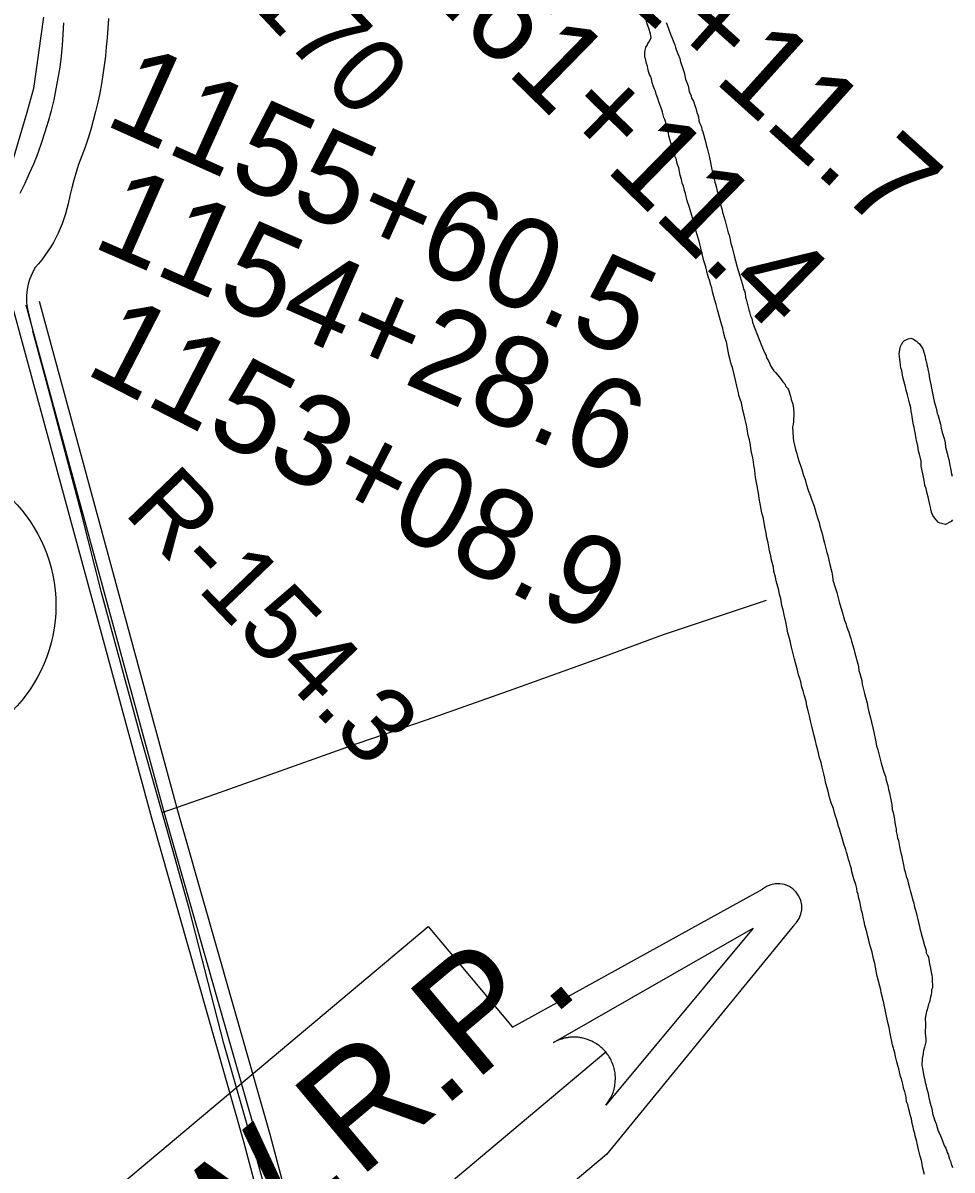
# Model space of a CAD drawing. Extents: x 3424494 to 3462436, y 522220 to 547718.
# Drawn here: x 3453024 to 3454050, y 543347 to 544612 of the extents above; entities that cross this region are included whole.
import ezdxf

# ---------------------------------------------------------------- set-up
doc = ezdxf.new("R2010")
doc.units = 0
for name, color, linetype in [('V-DTCH-CNTR', 7, 'Continuous'), ('V-RIVR-EDGE', 7, 'Continuous'), ('V-RIVR-RANG-IDEN', 7, 'Continuous'), ('V-ROAD-CNTR', 7, 'Continuous'), ('V-ROAD-IDEN', 7, 'Continuous'), ('V-SITE-VEGE', 7, 'Continuous'), ('V-SURV-IDEN', 7, 'Continuous'), ('V-TOPO-SHOR', 7, 'Continuous'), ('V-TOPO-WATR-IDEN', 7, 'Continuous')]:
    doc.layers.add(name, color=color, linetype=linetype)

msp = doc.modelspace()

# ---------------------------------------------------------------- linework, layer by layer
at = {"layer": 'V-DTCH-CNTR'}
for points in [[(3453118.5, 544617.4), (3453117.8, 544606.8), (3453116.9, 544596.2), (3453116.1, 544586), (3453115.1, 544575.7), (3453113.8, 544565.5), (3453112.4, 544555.3), (3453110.7, 544545.1), (3453108.8, 544535), (3453106.6, 544524.9), (3453104.3, 544514.9), (3453101.7, 544504.9), (3453098.9, 544495)], [(3453098.9, 544495), (3453095.9, 544485.2), (3453092.6, 544475.4), (3453089.2, 544465.7), (3453085.5, 544456.1), (3453082.7, 544447.6), (3453080.2, 544439), (3453077.9, 544430.3), (3453075.8, 544421.6), (3453073.9, 544412.9), (3453072.6, 544407.3), (3453071.1, 544401.8), (3453069.3, 544396.3), (3453067.4, 544390.9), (3453065.3, 544385.6), (3453062.9, 544380.4), (3453060.4, 544375.3), (3453057.7, 544370.2), (3453054.8, 544365.3), (3453051.7, 544360.5), (3453048.4, 544355.8), (3453045, 544351.2), (3453041.4, 544346.7), (3453037.6, 544342.4), (3453035.8, 544339.3), (3453034.1, 544336.1), (3453032.7, 544332.7), (3453031.4, 544329.3), (3453030.3, 544325.8), (3453029.4, 544322.3), (3453028.8, 544318.7), (3453028.3, 544315.1), (3453028, 544311.5), (3453028, 544307.9), (3453028.1, 544304.2)], [(3453028.1, 544304.2), (3453028.5, 544300.6), (3453029.1, 544297), (3453029.8, 544293.5), (3453034.8, 544272.3)], [(3453526.6, 542482.9), (3453494.5, 542596.8), (3453463.8, 542702.4), (3453443.7, 542773.5), (3453435, 542805), (3453408.4, 542903.2), (3453375.2, 543018.6), (3453344.3, 543135.1), (3453312.5, 543248.5), (3453281.6, 543361.9), (3453245.8, 543486.2), (3453207.7, 543635), (3453182.9, 543723.1), (3453177.7, 543741.2), (3453154.1, 543824.1), (3453111.1, 543982.6), (3453088.3, 544072.7), (3453054.8, 544198.9), (3453034.8, 544272.3)], [(3453177.7, 543741.2), (3453236, 543761.5), (3453318.8, 543790.6), (3453393.1, 543817.2), (3453470.8, 543843.7), (3453565.2, 543877.2), (3453663.6, 543912.7), (3453731.2, 543937.4), (3453788.7, 543956.5), (3453844.8, 543975.4)]]:
    msp.add_lwpolyline(points, dxfattribs=at)
at = {"layer": 'V-RIVR-EDGE'}
msp.add_spline([(3451748, 544260.9), (3451764.4, 544271.1), (3451791.5, 544289.6), (3451819.7, 544315.2), (3451837, 544333.4), (3451853.4, 544346.5), (3451865.5, 544357.5), (3451883.9, 544373.5), (3451891.9, 544381.9), (3451901.8, 544389.5), (3451915.4, 544400.1), (3451929.3, 544415.4), (3451940.3, 544428.2), (3451954.2, 544444.2), (3451972.9, 544464.7), (3451993.4, 544482.9), (3452012.5, 544495.6), (3452023.8, 544502.9), (3452039.2, 544516.4), (3452050.2, 544527), (3452059, 544538.3), (3452067.8, 544552.9), (3452074.8, 544560.5), (3452091.2, 544571.8), (3452115.8, 544592.6), (3452128.2, 544602.8), (3452139.6, 544615.2), (3452155, 544628.3), (3452167.4, 544638.5), (3452179.9, 544650.9), (3452198.2, 544669.2), (3452207.8, 544682.3), (3452220.6, 544695.1), (3452238.5, 544714), (3452251, 544727.5), (3452258.3, 544734.8), (3452278.1, 544758.5), (3452293.2, 544775.7), (3452312.6, 544794.6), (3452329.8, 544810.7), (3452335.3, 544823.1), (3452350, 544839.5), (3452364.7, 544859.2), (3452384.1, 544880), (3452409.4, 544913.9), (3452420.8, 544928.9), (3452427.4, 544943.5), (3452428.9, 544959.2), (3452432.2, 544966.5), (3452437.7, 544973.4), (3452456.7, 544992), (3452476.9, 545011.7), (3452493, 545024.9), (3452500.7, 545030.3), (3452509.5, 545042), (3452516.5, 545052.2), (3452530.4, 545063.1), (3452544.7, 545071.1), (3452550.5, 545081), (3452571.8, 545108.4), (3452596, 545136.1), (3452616.9, 545156.9), (3452640.7, 545180.6), (3452668.6, 545210.5), (3452708.1, 545250.6), (3452727.2, 545267), (3452748.8, 545279.4), (3452766.7, 545292.1), (3452778.5, 545308.2), (3452791.7, 545319.1), (3452841.5, 545350.8), (3452868.2, 545377), (3452890.6, 545399.3), (3452902.6, 545409.1), (3452913.3, 545420.1), (3452931.6, 545429.9), (3452944.8, 545441.2), (3452999.7, 545489.3), (3453027.2, 545515.6), (3453069, 545555.7), (3453103.4, 545592.5), (3453125.8, 545625.7), (3453154.4, 545652.3), (3453181.9, 545679.7), (3453207.5, 545702.3), (3453239.4, 545730.7), (3453267.7, 545752.5)], degree=3, dxfattribs=at)
at = {"layer": 'V-ROAD-CNTR'}
for points in [[(3453012.8, 544297.5), (3453165.8, 543735.1), (3453267.7, 543378.2), (3453416, 542818.1)], [(3453027.3, 544301.5), (3453180.3, 543739.2), (3453282.2, 543382.2), (3453431.5, 542817.9), (3453579.8, 542281.3), (3453694, 541871.9), (3453701.2, 541849.5)], [(3453041.8, 544305.4), (3453194.7, 543743.2), (3453296.6, 543386.2), (3453444.3, 542828.2)]]:
    msp.add_lwpolyline(points, dxfattribs=at)
msp.add_arc((3452629.4, 544625.1), 439.9, 332.8686, 358.3473, dxfattribs=at)
at = {"layer": 'V-ROAD-IDEN'}
msp.add_circle((3452895.4, 543969.7), 165, dxfattribs=at)
at = {"layer": 'V-SITE-VEGE'}
for points in [[(3453813.9, 544204.2), (3453812.1, 544211.5), (3453811, 544216.6), (3453807.4, 544232.1), (3453805.9, 544235.9), (3453804.5, 544242.1), (3453803.4, 544246), (3453800.5, 544260.4), (3453799.1, 544264.2), (3453797.3, 544271.2), (3453796.6, 544275.5), (3453795.1, 544280.1), (3453792.5, 544289.4), (3453790.7, 544295.7), (3453789.3, 544301.9), (3453787.8, 544306.5), (3453786.7, 544310.4), (3453785.3, 544315.8), (3453784.6, 544320.1), (3453783.5, 544323.2), (3453782, 544328.6), (3453780.9, 544331.7), (3453779.8, 544335.2), (3453778, 544343.4), (3453775.8, 544350), (3453770.4, 544371.7), (3453767.8, 544379.8), (3453764.9, 544389.9), (3453763.1, 544397.3), (3453759.8, 544408.9), (3453757.2, 544416.3), (3453755.4, 544424.4), (3453754.3, 544427.5), (3453753.3, 544432.2), (3453751.8, 544435.7), (3453751.1, 544439.6), (3453749.6, 544444.6), (3453748.2, 544452.4), (3453746.7, 544456.2), (3453746, 544458.6), (3453745.3, 544461.7), (3453744.1, 544464.8), (3453742, 544472.2), (3453740.1, 544477.6), (3453737.2, 544487.7), (3453736.5, 544490.8), (3453734.7, 544497), (3453734.3, 544499.3), (3453733.6, 544502.4), (3453732.5, 544505.9), (3453731.4, 544508.2), (3453729.9, 544514.1), (3453729.2, 544516.4), (3453728.4, 544518.3), (3453727.7, 544520.7), (3453725.9, 544525.3), (3453724.8, 544529.2), (3453722.9, 544533.9), (3453722.2, 544537), (3453721.1, 544539.3), (3453719.6, 544543.2), (3453718.5, 544546.7), (3453717.8, 544550.6), (3453716.7, 544553.7), (3453715.6, 544555.6), (3453714.8, 544557.6), (3453714.1, 544560.3), (3453713.4, 544564.9), (3453712.3, 544567.6), (3453711.6, 544571.5), (3453710.5, 544575), (3453710.6, 544580.4), (3453711.4, 544583.5), (3453711.8, 544585.8), (3453713, 544587.7), (3453713.8, 544589.6), (3453715.4, 544591.5), (3453717.4, 544596.5), (3453716.7, 544600), (3453714.9, 544606.6), (3453713, 544611.6), (3453711.6, 544617.1)], [(3453733.9, 544612.8), (3453736.5, 544606.2), (3453739.1, 544598.8), (3453740.6, 544595.7), (3453741.7, 544592.6), (3453743.5, 544588.3), (3453744.2, 544585.2), (3453745.4, 544582.1), (3453749.1, 544573.2), (3453749.8, 544569.7), (3453752.7, 544561.2), (3453753.8, 544557.7), (3453755.6, 544550.3), (3453758.2, 544542.9), (3453759.6, 544536.7), (3453761.5, 544532.1), (3453762.2, 544529.3), (3453764.1, 544526.2), (3453765.6, 544521.2), (3453766.7, 544518.5), (3453767.8, 544513.8)], [(3453767.8, 544513.8), (3453768.9, 544511.1), (3453769.6, 544508.8), (3453770.3, 544504.5), (3453771, 544502.2), (3453772.9, 544497.9), (3453773.6, 544494.8), (3453774.7, 544492.1), (3453778, 544480), (3453778.7, 544476.6), (3453779.4, 544474.2), (3453781.2, 544466.9), (3453782, 544463.8), (3453784.8, 544449), (3453786.6, 544441.7), (3453787.7, 544436.6), (3453788.4, 544434.7), (3453789.5, 544430.4), (3453790.2, 544426.9), (3453791.3, 544423.8), (3453793.1, 544415.7), (3453795.7, 544407.2), (3453796.4, 544403.7), (3453798.2, 544397.8), (3453799.3, 544394), (3453802.6, 544380.8), (3453803.7, 544378.1), (3453804.4, 544375.3), (3453805.5, 544369.2), (3453806.9, 544364.5), (3453809.5, 544354), (3453813.1, 544340.5), (3453815.7, 544332.3), (3453817.9, 544324.9), (3453818.6, 544322.2), (3453819.3, 544318.7), (3453820.4, 544316.8), (3453821.1, 544314.1), (3453821.8, 544309.8), (3453822.9, 544306.3), (3453825.5, 544295.8), (3453826.2, 544293.5), (3453827.3, 544289.2), (3453828.8, 544286.1), (3453829.5, 544282.3), (3453831.3, 544277.2), (3453832.8, 544273.3), (3453834.3, 544269.8), (3453836.1, 544264.8), (3453837.6, 544261.3), (3453838.7, 544258.2), (3453841.7, 544251.2), (3453843.2, 544247.3), (3453844.3, 544245.3), (3453845, 544243), (3453846.9, 544239.5), (3453848.4, 544236.4), (3453849.1, 544234.1), (3453852.9, 544228.6), (3453854.8, 544226.6), (3453859, 544221.5), (3453862.7, 544216.5), (3453865, 544214.1), (3453866.1, 544211.4), (3453868, 544209.4), (3453869.2, 544207.5), (3453871.4, 544200.5), (3453872.1, 544197), (3453873.9, 544191.9), (3453874.6, 544186.9), (3453874.9, 544182.3), (3453874.7, 544172.2), (3453874.3, 544169.5), (3453873.5, 544166.9), (3453874.4, 544154.5), (3453874.8, 544151.4), (3453876.9, 544141.7), (3453878.4, 544137.4), (3453879.1, 544133.9), (3453880.9, 544128.1), (3453882.4, 544124.2), (3453883.9, 544119.6), (3453885.7, 544113), (3453887.6, 544108.7), (3453888.6, 544104), (3453891.2, 544095.9), (3453893.1, 544091.2), (3453894.9, 544085.8), (3453897.5, 544079.2), (3453899.7, 544071), (3453901.5, 544065.2), (3453903, 544061.3), (3453903.7, 544057.1), (3453905.5, 544051.3), (3453906.6, 544047.4), (3453907.3, 544043.9), (3453908.8, 544038.5), (3453911.3, 544028), (3453912.4, 544024.9), (3453914.2, 544016.4), (3453917.1, 544006.3)], [(3454050.1, 544064.1), (3454048.6, 544062.2), (3454046.6, 544061.1), (3454042.3, 544058.8), (3454036.6, 544060.5), (3454034.7, 544061.3), (3454032, 544064), (3454030.1, 544066.3), (3454028.6, 544068.7), (3454027.1, 544072.6), (3454026.4, 544075.7), (3454025.7, 544078), (3454025, 544081.1), (3454023.9, 544085.7), (3454023.2, 544089.6), (3454022.1, 544093.1), (3454021, 544098.5), (3454019.6, 544102), (3454019.2, 544105.5), (3454017.5, 544114.7), (3454015.7, 544123.2), (3454015.7, 544126.3), (3454015.4, 544129), (3454013.6, 544136.4), (3454012.5, 544139.9), (3454011.8, 544146), (3454010.7, 544149.9), (3454009.7, 544155.7), (3454009.3, 544158.8), (3454008.6, 544161.9), (3454007.9, 544166.2), (3454007.2, 544168.5), (3454006.8, 544171.2), (3454006.1, 544175), (3454005.8, 544178.1), (3454005.1, 544180.5), (3454004.7, 544183.9), (3454004, 544187.8), (3454002.9, 544191.7), (3454000.4, 544202.1), (3453999, 544207.2), (3453998.3, 544211), (3453997.5, 544213.3), (3453995.4, 544221.5), (3453994.3, 544228.8), (3453993.2, 544231.9), (3453992.9, 544234.6), (3453992.2, 544238.5), (3453991.5, 544243.9), (3453991.2, 544247.4), (3453992, 544252), (3453992.8, 544255.4), (3453993.7, 544257.7), (3453995.2, 544260), (3453997.2, 544261.9), (3453999.5, 544263), (3454001.5, 544263.8), (3454004.2, 544264.5), (3454006.5, 544263.7), (3454010.3, 544261.3), (3454011.8, 544259.7), (3454013.7, 544258.2), (3454016, 544255), (3454017.5, 544252.7), (3454020, 544244.2), (3454020.4, 544241.5), (3454021.5, 544237.6), (3454021.8, 544235.3), (3454022.5, 544232.6), (3454023.2, 544228.7), (3454023.9, 544225.6), (3454024.6, 544220.2), (3454026.1, 544213.3), (3454027.5, 544207.4), (3454030, 544194.7), (3454032.2, 544187.3), (3454033.2, 544181.9), (3454034.3, 544178.8), (3454036.9, 544169.5), (3454037.6, 544165.3), (3454038.7, 544160.6), (3454040.9, 544153.7)], [(3453949.1, 543637), (3453947.7, 543642.8), (3453946.6, 543646.3), (3453945.9, 543651), (3453944.8, 543653.7), (3453944.4, 543657.2), (3453943.4, 543661.8), (3453941.1, 543668), (3453939, 543675.8), (3453938.6, 543678.9), (3453937.2, 543683.2), (3453936.4, 543686.3), (3453935.3, 543689.4), (3453934.2, 543694), (3453933.1, 543697.5), (3453932.4, 543700.2), (3453930.6, 543704.9), (3453928, 543714.2), (3453926.6, 543718.9), (3453925.5, 543723.1), (3453924.4, 543725.8), (3453923.6, 543728.9), (3453922.2, 543734), (3453921.1, 543737.1), (3453920, 543740.6), (3453918.9, 543745.6), (3453916.3, 543751.8), (3453914.1, 543759.2), (3453913, 543764.6), (3453910.5, 543773.2), (3453909.4, 543779), (3453908, 543783.7), (3453906.2, 543791), (3453905.1, 543796.1), (3453903.2, 543801.5), (3453901.5, 543810), (3453900, 543815.1), (3453898.9, 543820.1), (3453897.1, 543827.1), (3453894.6, 543837.9), (3453893.5, 543842.2), (3453892.8, 543846.1), (3453891, 543853.4), (3453889.5, 543858.9), (3453888.5, 543863.9), (3453886.3, 543870.9), (3453885.2, 543875.5), (3453883.7, 543879.4), (3453882.6, 543885.2), (3453881.6, 543889.1), (3453880.1, 543893), (3453878.6, 543899.6), (3453875.7, 543910.4), (3453872.1, 543925.2), (3453871.1, 543930.6), (3453868.5, 543939.5), (3453867.1, 543945.7), (3453866, 543951.5), (3453864.2, 543959.3), (3453863.1, 543964.7), (3453861.7, 543969.4), (3453860.6, 543977.1), (3453859.2, 543981.8), (3453858.5, 543986.4), (3453856.7, 543992.6), (3453855.6, 543996.9), (3453854.9, 544000.8), (3453853, 544007.4), (3453852.4, 544012), (3453850.5, 544019.4), (3453849.5, 544024.4), (3453848, 544029.8), (3453846.6, 544038.7), (3453845.2, 544044.2), (3453844.5, 544049.2), (3453843.1, 544056.2), (3453841.7, 544065.5), (3453839.8, 544071.7), (3453839.1, 544075.9), (3453836.6, 544087.6), (3453836.3, 544091.4), (3453834.6, 544101.5), (3453832.8, 544110.8), (3453832.5, 544114.6), (3453831.8, 544118.9), (3453830.7, 544124.3), (3453830.4, 544128.2), (3453829.7, 544132.5), (3453828.2, 544138.7), (3453827.5, 544142.9), (3453827.2, 544146.8), (3453826.1, 544152.2), (3453825, 544156.1), (3453824.3, 544159.2), (3453823.6, 544164.6), (3453822.6, 544168.5), (3453820, 544179.7), (3453818.6, 544185.2), (3453817.2, 544193.3), (3453814.2, 544201.4), (3453813.9, 544204.2)], [(3454040.9, 544153.7), (3454041.9, 544149), (3454042.6, 544144.4), (3454044.1, 544137.8), (3454045.1, 544134.3)], [(3454045.1, 544134.3), (3454046.2, 544130.8), (3454046.9, 544126.6), (3454047.3, 544123.9), (3454048, 544121.2), (3454049.1, 544115), (3454049.8, 544112.3)], [(3453917.1, 544006.3), (3453917.8, 544002), (3453918.1, 543997.8), (3453920, 543991.6), (3453922.5, 543983.8), (3453925.1, 543973.7), (3453928, 543963.6), (3453929.1, 543960.1), (3453929.8, 543957), (3453931.3, 543952.4), (3453932.4, 543949.6), (3453933.1, 543946.9), (3453934.6, 543942.7), (3453935.7, 543940.3), (3453936.4, 543937.6), (3453937.9, 543933.3), (3453938.6, 543930.2), (3453941.2, 543921.7), (3453942.3, 543917), (3453945.5, 543905), (3453946.2, 543901.9), (3453946.9, 543897.7), (3453947.7, 543894.6), (3453949.9, 543886.8), (3453950.6, 543882.9), (3453953.1, 543872.5), (3453956, 543861.6), (3453956.7, 543857), (3453957.8, 543852.3), (3453959.6, 543845.7), (3453963.2, 543829.8), (3453965.3, 543820.9), (3453966.4, 543814.7), (3453967.9, 543810.4), (3453971.5, 543795.7), (3453972.6, 543791.8), (3453974.4, 543785.6), (3453976.3, 543781), (3453977, 543776.7), (3453978.8, 543770.9), (3453979.5, 543766.6), (3453980.6, 543762.7), (3453981.6, 543756.9), (3453983.1, 543750), (3453983.7, 543744.5), (3453984.5, 543741), (3453986.3, 543733.7), (3453986.6, 543730.2), (3453987.3, 543725.9), (3453988, 543723.2), (3453988, 543720.1), (3453989.1, 543715.9), (3453989.4, 543712.8), (3453990.5, 543710.1), (3453991.5, 543703.5), (3453992.3, 543700), (3453994.1, 543692.2), (3453994.8, 543688.4), (3453996.2, 543683.3), (3453996.9, 543679.1), (3453998, 543675.6), (3453999.1, 543670.5), (3454000.6, 543667), (3454001.3, 543663.5), (3454002.8, 543658.1), (3454003.5, 543655), (3454004.9, 543650), (3454006.4, 543644.2), (3454007.5, 543641), (3454008.2, 543636.8), (3454009.3, 543633.3), (3454010, 543630.6), (3454012.5, 543619.7), (3454013.6, 543615.8), (3454014, 543613.1), (3454015.1, 543609.3), (3454015.8, 543606.2), (3454017.6, 543600), (3454019.1, 543594.5), (3454020.9, 543588.7), (3454021.2, 543586.4), (3454022.7, 543583.3), (3454023.5, 543581.3), (3454024.5, 543576.3), (3454024.9, 543574), (3454026, 543569.3), (3454026.7, 543564.7), (3454027.4, 543561.9), (3454027.7, 543558.9), (3454027.6, 543553.8), (3454028, 543551.5), (3454027.9, 543547.7), (3454027.1, 543545.4), (3454027.1, 543543), (3454026.6, 543540), (3454025.8, 543537.7), (3454024.6, 543531.9), (3454023.8, 543529.6), (3454022.1, 543523.4), (3454021.3, 543521.5), (3454020.4, 543516.1)], [(3454019.4, 543341.6), (3454016.9, 543350.2), (3454016.5, 543352.9), (3454015.8, 543357.1), (3454014.4, 543361.8), (3454012.6, 543369.2), (3454011.1, 543375.7), (3454010.8, 543378.1), (3454009, 543384.3), (3454008.6, 543387), (3454007.1, 543391.2), (3454006.8, 543394.3), (3454005.7, 543397.8), (3454005, 543402.9), (3454003.9, 543406.4), (3454003.2, 543409.8), (3454001.4, 543415.3), (3454000.7, 543418.8), (3453999.5, 543421.9), (3453998.9, 543426.9), (3453997.4, 543432.7), (3453995.9, 543437), (3453995.6, 543439.7), (3453994.9, 543442.8), (3453993.8, 543447.1), (3453992.7, 543449.8), (3453990.9, 543458.3), (3453989.8, 543461.8), (3453988.7, 543466.1), (3453987.3, 543471.9), (3453986.6, 543475.8), (3453984, 543484.7), (3453981.5, 543497.1), (3453980.1, 543503.7), (3453978.6, 543509.5), (3453974.4, 543530.8), (3453972.9, 543537), (3453971.5, 543542.4), (3453971.1, 543545.5), (3453967.5, 543559.1), (3453966.8, 543562.2), (3453964.3, 543574.6), (3453962.8, 543579.6), (3453961.4, 543587), (3453959.6, 543592.8), (3453958.5, 543596.7), (3453957.8, 543600.2), (3453956.3, 543605.6), (3453955.6, 543609.5), (3453954.1, 543614.1), (3453953.4, 543616.9), (3453952.7, 543620.7), (3453952, 543623.8), (3453950.9, 543629.6), (3453949.8, 543633.1), (3453949.1, 543637)], [(3454020.4, 543516.1), (3454020, 543513.4), (3454020.3, 543507.6), (3454020.1, 543497.2), (3454020.8, 543491.8), (3454020.7, 543487.9), (3454019.1, 543482.2), (3454018.3, 543478.3), (3454017.4, 543472.9), (3454016.6, 543469.5), (3454016.4, 543461.8), (3454017.2, 543459), (3454017.5, 543456.3), (3454018.6, 543450.1), (3454019.3, 543447.4), (3454020, 543443.5), (3454020.7, 543440.8), (3454021.4, 543437.3), (3454022.9, 543432.3), (3454024.3, 543424.9), (3454026.1, 543417.6), (3454027.2, 543414.5), (3454027.6, 543411.4), (3454028.6, 543407.5), (3454029.4, 543404.4), (3454030.1, 543402.1), (3454032, 543397.4), (3454034.5, 543389.6), (3454035.6, 543387.7), (3454037.1, 543383.4), (3454041.2, 543372.9), (3454042.7, 543370.6), (3454043.4, 543368.6), (3454044.2, 543365.9), (3454045.3, 543364), (3454046.7, 543358.5), (3454047.9, 543356.2), (3454048.6, 543353.5), (3454050.1, 543349.2)]]:
    msp.add_lwpolyline(points, dxfattribs=at)
at = {"layer": 'V-TOPO-SHOR'}
msp.add_lwpolyline([(3453046.6, 544618.7), (3453035.7, 544540.1), (3453028.4, 544513.5), (3453022.6, 544493.7), (3453013.2, 544462.4), (3453003.8, 544434.5), (3452991, 544404.5), (3452970.6, 544376.8), (3452932, 544317.2), (3452925, 544309.1), (3452798.9, 544183.8), (3452667.9, 544048.3), (3452537.5, 543911.4), (3452402.3, 543769.9), (3452229.5, 543596.7), (3452099.2, 543461.9), (3452035.1, 543395.9), (3451996.9, 543365.7)], dxfattribs=at)
at = {"layer": 'V-TOPO-WATR-IDEN'}
msp.add_line((3453091.7, 542994.2), (3453667.3, 543476.8), dxfattribs=at)
for points in [[(3452884.6, 542855.1), (3453075, 543094), (3452982.1, 543204.9), (3453471.3, 543615.2), (3453564.3, 543504.3), (3453840.3, 543656.4)], [(3453874.4, 543615.8), (3453668.3, 543363.8), (3453512.4, 543233.1), (3453612.2, 543114.1), (3453467.3, 542992.6), (3453367.5, 543111.6), (3453195.2, 542967.2), (3452918.7, 542814.5)]]:
    msp.add_lwpolyline(points, dxfattribs=at)
msp.add_lwpolyline([(3453609.7, 543487.2), (3453830.1, 543613.3), (3453667.5, 543418.2), (3453670.2, 543421.9), (3453672.5, 543425.7), (3453673.3, 543427.2), (3453674, 543428.7), (3453674.7, 543430.4), (3453675.4, 543432.1), (3453675.9, 543433.6), (3453676.5, 543435.7), (3453677, 543438), (3453677.3, 543439.2), (3453677.5, 543440.9), (3453677.8, 543443.1), (3453677.9, 543444.8), (3453678, 543446.7), (3453678, 543447.9), (3453678, 543449.2), (3453677.9, 543450.9), (3453677.7, 543452.4), (3453677.6, 543453.9), (3453677.4, 543455.1), (3453677, 543456.9), (3453676.6, 543458.6), (3453676.3, 543459.9), (3453675.8, 543461.5), (3453675.3, 543462.9), (3453674.9, 543464.1), (3453674.5, 543465), (3453673.9, 543466.4), (3453673.2, 543467.8), (3453672.6, 543469.1), (3453671.8, 543470.4), (3453671.1, 543471.5), (3453670.3, 543472.8), (3453669.6, 543473.8), (3453668.6, 543475.3), (3453667.3, 543476.8), (3453666.9, 543477.3), (3453666.3, 543478), (3453665.5, 543478.8), (3453664.8, 543479.6), (3453664.1, 543480.3), (3453663.3, 543481), (3453662.5, 543481.8), (3453661.8, 543482.3), (3453660.9, 543483.1), (3453660, 543483.8), (3453659.4, 543484.3), (3453657.7, 543485.4), (3453656.8, 543486), (3453656.2, 543486.4), (3453655.1, 543487), (3453654.2, 543487.6), (3453653.2, 543488.1), (3453652, 543488.7), (3453650.8, 543489.2), (3453649.9, 543489.6), (3453649.1, 543489.9), (3453648.1, 543490.3), (3453647.1, 543490.7), (3453646, 543491.1), (3453644.8, 543491.4), (3453643.6, 543491.7), (3453642.1, 543492.1), (3453641, 543492.3), (3453639.8, 543492.5), (3453638.6, 543492.7), (3453637.7, 543492.8), (3453636.6, 543493), (3453635.1, 543493.1), (3453635, 543493.1), (3453634.1, 543493.1), (3453633.4, 543493.1), (3453632.3, 543493.2), (3453631.1, 543493.1), (3453630, 543493.1), (3453629.1, 543493.1), (3453627.9, 543493), (3453626.8, 543492.8), (3453626, 543492.7), (3453624.9, 543492.6), (3453623.5, 543492.3), (3453622.7, 543492.1), (3453622, 543492), (3453621.4, 543491.9), (3453620.7, 543491.7), (3453619.7, 543491.4), (3453618.8, 543491.1), (3453617.9, 543490.8), (3453616.9, 543490.5), (3453615.8, 543490.1), (3453615.1, 543489.8), (3453614, 543489.4), (3453612.7, 543488.8), (3453611.8, 543488.3), (3453611.1, 543488), (3453610.5, 543487.6), (3453610, 543487.4)], close=True, dxfattribs=at)
msp.add_arc((3453857.3, 543636.1), 26.5, 309.9794, 129.9794, dxfattribs=at)

# ---------------------------------------------------------------- texts
at = {"layer": 'V-RIVR-RANG-IDEN'}
for s, rotation, p in [('D-170', 313.2303, (3453189.1, 544723.6)), ('R-154.3', 313.8967, (3453133.9, 544071.9))]:
    msp.add_text(s, height=83, rotation=rotation, dxfattribs=at).set_placement(p)
at = {"layer": 'V-SURV-IDEN'}
for s, rotation, p in [('1162+11.7', 318.0039, (3453506, 544800.3)), ('1161+11.4', 315.5943, (3453397, 544713.9)), ('1155+60.5', 335.8129, (3453111.7, 544501.2)), ('1154+28.6', 336.3379, (3453098.3, 544366.4)), ('1153+08.9', 332.7861, (3453090.2, 544226.8))]:
    msp.add_text(s, height=100, rotation=rotation, dxfattribs=at).set_placement(p)
at = {"layer": 'V-TOPO-WATR-IDEN'}
msp.add_text('L.W.R.P.', height=124.5, rotation=39.9793, dxfattribs=at).set_placement((3453132, 543116))

doc.saveas('drawing.dxf')
